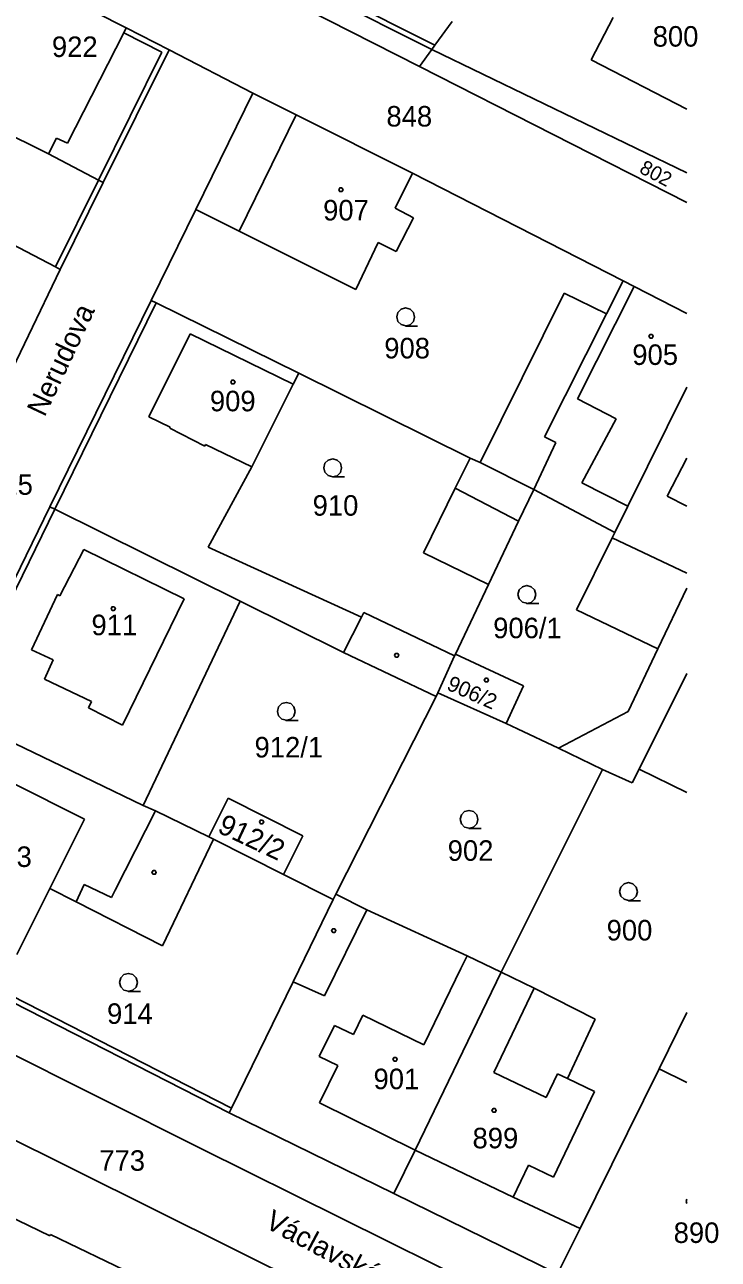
# Model space of a CAD drawing. Extents: x -621797 to -620972, y -1175539 to -1174697.
# Drawn here: x -621032.1 to -620974.5, y -1175296.1 to -1175193.8 of the extents above; entities that cross this region are included whole.
import ezdxf

# ---------------------------------------------------------------- set-up
doc = ezdxf.new("R2010")
doc.units = 0
for name, color, linetype in [('INZ mimo EON - nadz', 7, 'Continuous'), ('Rozvod plynu EON', 7, 'Continuous'), ('SDEL EON', 7, 'Continuous'), ('SDEL EON - popis', 7, 'Continuous'), ('Silnoproud EON', 7, 'Continuous'), ('Silnoproud EON - popis', 7, 'Continuous')]:
    doc.layers.add(name, color=color, linetype=linetype)

msp = doc.modelspace()

# ---------------------------------------------------------------- linework, layer by layer
at = {"layer": 'Rozvod plynu EON'}
for points in [[(-621005.74, -1175207.3), (-621005.65, -1175207.45), (-621005.74, -1175207.6), (-621005.92, -1175207.6), (-621006.01, -1175207.45), (-621005.92, -1175207.3)], [(-620980.01, -1175219.43), (-620979.92, -1175219.58), (-620980.01, -1175219.73), (-620980.19, -1175219.73), (-620980.28, -1175219.58), (-620980.19, -1175219.43)], [(-621014.7, -1175223.23), (-621014.61, -1175223.38), (-621014.7, -1175223.53), (-621014.88, -1175223.53), (-621014.97, -1175223.38), (-621014.88, -1175223.23)], [(-621024.62, -1175242), (-621024.53, -1175242.15), (-621024.62, -1175242.3), (-621024.8, -1175242.3), (-621024.89, -1175242.15), (-621024.8, -1175242)], [(-621001.12, -1175245.86), (-621001.03, -1175246.01), (-621001.12, -1175246.16), (-621001.3, -1175246.16), (-621001.39, -1175246.01), (-621001.3, -1175245.86)], [(-620993.67, -1175247.92), (-620993.58, -1175248.07), (-620993.67, -1175248.22), (-620993.85, -1175248.22), (-620993.94, -1175248.07), (-620993.85, -1175247.92)], [(-621012.32, -1175259.67), (-621012.23, -1175259.82), (-621012.32, -1175259.97), (-621012.5, -1175259.97), (-621012.59, -1175259.82), (-621012.5, -1175259.67)], [(-621021.23, -1175263.85), (-621021.14, -1175264), (-621021.23, -1175264.15), (-621021.41, -1175264.15), (-621021.5, -1175264), (-621021.41, -1175263.85)], [(-621006.33, -1175268.67), (-621006.24, -1175268.82), (-621006.33, -1175268.97), (-621006.51, -1175268.97), (-621006.6, -1175268.82), (-621006.51, -1175268.67)], [(-621001.24, -1175279.33), (-621001.15, -1175279.48), (-621001.24, -1175279.63), (-621001.42, -1175279.63), (-621001.51, -1175279.48), (-621001.42, -1175279.33)], [(-620993.03, -1175283.57), (-620992.94, -1175283.72), (-620993.03, -1175283.87), (-620993.21, -1175283.87), (-620993.3, -1175283.72), (-620993.21, -1175283.57)]]:
    msp.add_lwpolyline(points, close=True, dxfattribs=at)
at = {"layer": 'SDEL EON'}
for points in [[(-621000.45, -1175218.72), (-621000.83, -1175218.62), (-621001.1, -1175218.35), (-621001.2, -1175217.98), (-621001.1, -1175217.61), (-621000.83, -1175217.34), (-621000.46, -1175217.24), (-621000.09, -1175217.34), (-620999.82, -1175217.61), (-620999.72, -1175217.99), (-620999.82, -1175218.37), (-621000.09, -1175218.64), (-621000.47, -1175218.74), (-620999.47, -1175218.74)], [(-621006.5, -1175231.22), (-621006.88, -1175231.12), (-621007.15, -1175230.85), (-621007.25, -1175230.48), (-621007.15, -1175230.11), (-621006.88, -1175229.84), (-621006.51, -1175229.74), (-621006.14, -1175229.84), (-621005.87, -1175230.11), (-621005.77, -1175230.49), (-621005.87, -1175230.87), (-621006.14, -1175231.14), (-621006.52, -1175231.24), (-621005.52, -1175231.24)], [(-620990.4, -1175241.71), (-620990.78, -1175241.61), (-620991.05, -1175241.34), (-620991.15, -1175240.97), (-620991.05, -1175240.6), (-620990.78, -1175240.33), (-620990.41, -1175240.23), (-620990.04, -1175240.33), (-620989.77, -1175240.6), (-620989.67, -1175240.98), (-620989.77, -1175241.36), (-620990.04, -1175241.63), (-620990.42, -1175241.73), (-620989.42, -1175241.73)], [(-621010.35, -1175251.4), (-621010.73, -1175251.3), (-621011, -1175251.03), (-621011.1, -1175250.66), (-621011, -1175250.29), (-621010.73, -1175250.02), (-621010.36, -1175249.92), (-621009.99, -1175250.02), (-621009.72, -1175250.29), (-621009.62, -1175250.67), (-621009.72, -1175251.05), (-621009.99, -1175251.32), (-621010.37, -1175251.42), (-621009.37, -1175251.42)], [(-620995.19, -1175260.34), (-620995.57, -1175260.24), (-620995.84, -1175259.97), (-620995.94, -1175259.6), (-620995.84, -1175259.23), (-620995.57, -1175258.96), (-620995.2, -1175258.86), (-620994.83, -1175258.96), (-620994.56, -1175259.23), (-620994.46, -1175259.61), (-620994.56, -1175259.99), (-620994.83, -1175260.26), (-620995.21, -1175260.36), (-620994.21, -1175260.36)], [(-620981.97, -1175266.33), (-620982.35, -1175266.23), (-620982.62, -1175265.96), (-620982.72, -1175265.59), (-620982.62, -1175265.22), (-620982.35, -1175264.95), (-620981.98, -1175264.85), (-620981.61, -1175264.95), (-620981.34, -1175265.22), (-620981.24, -1175265.6), (-620981.34, -1175265.98), (-620981.61, -1175266.25), (-620981.99, -1175266.35), (-620980.99, -1175266.35)], [(-621023.44, -1175273.85), (-621023.82, -1175273.75), (-621024.09, -1175273.48), (-621024.19, -1175273.11), (-621024.09, -1175272.74), (-621023.82, -1175272.47), (-621023.45, -1175272.37), (-621023.08, -1175272.47), (-621022.81, -1175272.74), (-621022.71, -1175273.12), (-621022.81, -1175273.5), (-621023.08, -1175273.77), (-621023.46, -1175273.87), (-621022.46, -1175273.87)], [(-620977.15, -1175291.445), (-620977.2, -1175291.26), (-620977.15, -1175291.075)]]:
    msp.add_lwpolyline(points, dxfattribs=at)
at = {"layer": 'SDEL EON - popis'}
for p, q in [((-621022.58, -1175183.6), (-620998.3, -1175195.84)), ((-620998.04, -1175195.48), (-621022.32, -1175183.23)), ((-620985.07, -1175196.69), (-620983.25, -1175193.18)), ((-621023.84, -1175194.44), (-621023.64, -1175194.04)), ((-621028.51, -1175203.6), (-621023.84, -1175194.44)), ((-621020.67, -1175196.05), (-621023.84, -1175194.44)), ((-621025.93, -1175206.64), (-621020.67, -1175196.05)), ((-620977.15, -1175200.759), (-620985.07, -1175196.69)), ((-621009.53, -1175201.25), (-621014.26, -1175210.89)), ((-621030.07, -1175204.47), (-621029.42, -1175203.16)), ((-621029.42, -1175203.16), (-621028.51, -1175203.6)), ((-621029.51, -1175213.83), (-621025.93, -1175206.64)), ((-620981.5, -1175215.47), (-620986.2, -1175224.77)), ((-621029.56, -1175233.92), (-621021.15, -1175216.82)), ((-620987.32, -1175216.01), (-620994.28, -1175230.04)), ((-620983.81, -1175217.74), (-620987.32, -1175216.01)), ((-621018.32, -1175219.38), (-621021.77, -1175226.26)), ((-621009.79, -1175223.55), (-621018.32, -1175219.38)), ((-620986.2, -1175224.77), (-620983.01, -1175226.43)), ((-621021.77, -1175226.26), (-621019.99, -1175227.12)), ((-620983.01, -1175226.43), (-620985.84, -1175231.72)), ((-621019.99, -1175227.12), (-621020.02, -1175227.19)), ((-621020.02, -1175227.19), (-621017.11, -1175228.68)), ((-621017.11, -1175228.68), (-621017.05, -1175228.55)), ((-621017.05, -1175228.55), (-621013.22, -1175230.41)), ((-620995.11, -1175229.67), (-620996.35, -1175232.18)), ((-620977.15, -1175229.681), (-620978.77, -1175232.84)), ((-620996.35, -1175232.18), (-620998.99, -1175237.53)), ((-620996.35, -1175232.18), (-620991.09, -1175234.9)), ((-620985.84, -1175231.72), (-620982.03, -1175233.65)), ((-620978.77, -1175232.84), (-620977.15, -1175233.661)), ((-621037.87, -1175250.93), (-621029.56, -1175233.92)), ((-620983.33, -1175236.28), (-620977.15, -1175239.212)), ((-621029.15, -1175241.09), (-621027.15, -1175237.26)), ((-621027.15, -1175237.26), (-621018.82, -1175241.35)), ((-620998.99, -1175237.53), (-620993.59, -1175240.15)), ((-621031.5, -1175245.55), (-621029.34, -1175240.99)), ((-621029.34, -1175240.99), (-621029.15, -1175241.09)), ((-621018.82, -1175241.35), (-621023.93, -1175251.8)), ((-621004.12, -1175242.87), (-621005.6, -1175245.77)), ((-621029.68, -1175246.4), (-621031.5, -1175245.55)), ((-621030.42, -1175247.98), (-621029.68, -1175246.4)), ((-621026.52, -1175249.83), (-621030.42, -1175247.98)), ((-621026.76, -1175250.38), (-621026.52, -1175249.83)), ((-621023.93, -1175251.8), (-621026.76, -1175250.38)), ((-621027.08, -1175259.59), (-621033.2, -1175256.52)), ((-621029.98, -1175265.34), (-621027.08, -1175259.59)), ((-621021.21, -1175258.89), (-621024.54, -1175265.47)), ((-621027.12, -1175264.99), (-621027.79, -1175266.45)), ((-621024.85, -1175266.08), (-621027.12, -1175264.99)), ((-621024.54, -1175265.47), (-621024.85, -1175266.08)), ((-621003.67, -1175267.1), (-621007.2, -1175274.24)), ((-621043.01, -1175269.19), (-621014.89, -1175283.52)), ((-620995.36, -1175270.92), (-620995.87, -1175271.97)), ((-621048.05, -1175271.55), (-621017.38, -1175286.89)), ((-620995.87, -1175271.97), (-620998.96, -1175278.3)), ((-621007.2, -1175274.24), (-621009.78, -1175273.06)), ((-620989.81, -1175273.6), (-620993.15, -1175280.57)), ((-621053.99, -1175275.68), (-620977.15, -1175313.878)), ((-621004, -1175275.83), (-621004.79, -1175277.43)), ((-620998.96, -1175278.3), (-621004, -1175275.83)), ((-621006.36, -1175276.69), (-621007.63, -1175279.25)), ((-621004.79, -1175277.43), (-621006.36, -1175276.69)), ((-621007.63, -1175279.25), (-621006.07, -1175280.01)), ((-621006.07, -1175280.01), (-621007.6, -1175283.09)), ((-620993.15, -1175280.57), (-620988.82, -1175282.64)), ((-620988.82, -1175282.64), (-620987.88, -1175280.68)), ((-620987.88, -1175280.68), (-620987.03, -1175281.08)), ((-621007.6, -1175283.09), (-620999.66, -1175287)), ((-621017.38, -1175286.89), (-620977.15, -1175306.845)), ((-620999.66, -1175287), (-620991.54, -1175290.92))]:
    msp.add_line(p, q, dxfattribs=at)
at = {"layer": 'Silnoproud EON'}
for p, q in [((-620999.31, -1175197.24), (-621023.4, -1175185)), ((-621023.64, -1175194.04), (-621034.16, -1175188.68)), ((-621020.06, -1175195.86), (-621023.64, -1175194.04)), ((-620996.61, -1175193.5), (-620998.04, -1175195.48)), ((-621025.53, -1175206.85), (-621020.06, -1175195.86)), ((-621013.12, -1175199.45), (-621020.06, -1175195.86)), ((-620998.3, -1175195.84), (-620999.31, -1175197.24)), ((-620998.04, -1175195.48), (-620998.3, -1175195.84)), ((-620977.15, -1175206.036), (-620998.3, -1175195.84)), ((-620977.15, -1175208.495), (-620999.31, -1175197.24)), ((-621017.85, -1175209.08), (-621013.12, -1175199.45)), ((-621009.53, -1175201.25), (-621013.12, -1175199.45)), ((-620999.89, -1175206.07), (-621009.53, -1175201.25)), ((-621030.07, -1175204.47), (-621034.83, -1175202.12)), ((-621025.93, -1175206.64), (-621030.07, -1175204.47)), ((-621045.53, -1175205.46), (-621029.51, -1175213.83)), ((-620999.89, -1175206.07), (-621001.32, -1175208.97)), ((-620982.43, -1175215), (-620999.89, -1175206.07)), ((-621029.11, -1175214.04), (-621025.53, -1175206.85)), ((-621025.53, -1175206.85), (-621025.93, -1175206.64)), ((-621021.56, -1175216.62), (-621017.85, -1175209.08)), ((-621014.26, -1175210.89), (-621017.85, -1175209.08)), ((-621001.32, -1175208.97), (-620999.82, -1175209.76)), ((-620999.82, -1175209.76), (-621001.24, -1175212.56)), ((-621004.6, -1175215.7), (-621014.26, -1175210.89)), ((-621002.73, -1175211.81), (-621004.6, -1175215.7)), ((-621001.24, -1175212.56), (-621002.73, -1175211.81)), ((-621035.46, -1175227.24), (-621029.11, -1175214.04)), ((-621029.51, -1175213.83), (-621029.11, -1175214.04)), ((-620983.81, -1175217.74), (-620982.43, -1175215)), ((-620981.5, -1175215.47), (-620982.43, -1175215)), ((-620977.15, -1175217.693), (-620981.5, -1175215.47)), ((-621029.96, -1175233.72), (-621021.56, -1175216.62)), ((-621021.15, -1175216.82), (-621021.56, -1175216.62)), ((-621009.33, -1175222.65), (-621021.15, -1175216.82)), ((-620988.94, -1175227.93), (-620983.81, -1175217.74)), ((-621009.33, -1175222.65), (-621009.79, -1175223.55)), ((-620995.11, -1175229.67), (-621009.33, -1175222.65)), ((-621009.79, -1175223.55), (-621013.22, -1175230.41)), ((-620982.03, -1175233.65), (-620977.15, -1175223.81)), ((-620988, -1175228.39), (-620988.94, -1175227.93)), ((-620989.84, -1175232.27), (-620988, -1175228.39)), ((-620994.28, -1175230.04), (-620995.11, -1175229.67)), ((-620989.84, -1175232.27), (-620994.28, -1175230.04)), ((-621013.22, -1175230.41), (-621016.84, -1175237.05)), ((-620991.09, -1175234.9), (-620989.84, -1175232.27)), ((-620983.11, -1175235.83), (-620989.84, -1175232.27)), ((-621038.28, -1175250.73), (-621029.96, -1175233.72)), ((-621029.56, -1175233.92), (-621029.96, -1175233.72)), ((-621014.17, -1175241.53), (-621029.56, -1175233.92)), ((-620983.11, -1175235.83), (-620982.03, -1175233.65)), ((-620993.59, -1175240.15), (-620991.09, -1175234.9)), ((-620986.28, -1175242.24), (-620983.33, -1175236.28)), ((-620983.33, -1175236.28), (-620983.11, -1175235.83)), ((-621016.84, -1175237.05), (-621004.12, -1175242.87)), ((-620996.33, -1175245.92), (-620993.59, -1175240.15)), ((-620979.54, -1175245.49), (-620977.15, -1175240.452)), ((-621014.17, -1175241.53), (-621022.24, -1175258.46)), ((-621005.6, -1175245.77), (-621014.17, -1175241.53)), ((-620979.54, -1175245.49), (-620986.28, -1175242.24)), ((-621004.12, -1175242.87), (-621003.92, -1175242.48)), ((-621003.92, -1175242.48), (-620996.4, -1175246.06)), ((-620982, -1175250.66), (-620979.54, -1175245.49)), ((-620997.93, -1175249.42), (-621005.6, -1175245.77)), ((-620997.8, -1175249.12), (-620996.4, -1175246.06)), ((-620996.4, -1175246.06), (-620996.33, -1175245.92)), ((-620996.33, -1175245.92), (-620990.68, -1175248.54)), ((-620981.1, -1175255.46), (-620977.15, -1175247.515)), ((-620990.68, -1175248.54), (-620992.13, -1175251.67)), ((-621006.24, -1175265.8), (-620997.93, -1175249.42)), ((-620997.93, -1175249.42), (-620997.8, -1175249.12)), ((-620997.8, -1175249.12), (-620992.13, -1175251.67)), ((-621029.04, -1175255.18), (-621037.87, -1175250.93)), ((-620987.79, -1175253.72), (-620982, -1175250.66)), ((-620992.13, -1175251.67), (-620991.17, -1175252.1)), ((-620991.17, -1175252.1), (-620987.79, -1175253.72)), ((-620987.79, -1175253.72), (-620984.13, -1175255.48)), ((-621026.35, -1175256.48), (-621029.04, -1175255.18)), ((-620992.53, -1175272.26), (-620984.13, -1175255.48)), ((-620984.13, -1175255.48), (-620981.67, -1175256.59)), ((-620981.67, -1175256.59), (-620981.1, -1175255.46)), ((-620977.15, -1175257.387), (-620981.1, -1175255.46)), ((-621022.24, -1175258.46), (-621026.35, -1175256.48)), ((-621021.21, -1175258.89), (-621022.24, -1175258.46)), ((-621016.78, -1175261.06), (-621015.17, -1175257.85)), ((-621015.17, -1175257.85), (-621008.98, -1175260.97)), ((-621016.78, -1175261.06), (-621021.21, -1175258.89)), ((-621016.39, -1175261.25), (-621020.61, -1175270.09)), ((-621016.39, -1175261.25), (-621016.78, -1175261.06)), ((-621010.59, -1175264.18), (-621016.39, -1175261.25)), ((-621008.98, -1175260.97), (-621010.59, -1175264.18)), ((-621006.47, -1175266.26), (-621010.59, -1175264.18)), ((-621029.98, -1175265.34), (-621032.7, -1175270.8)), ((-621027.79, -1175266.45), (-621029.98, -1175265.34)), ((-621006.47, -1175266.26), (-621006.24, -1175265.8)), ((-621006.24, -1175265.8), (-621003.67, -1175267.1)), ((-621020.61, -1175270.09), (-621027.79, -1175266.45)), ((-621009.78, -1175273.06), (-621006.47, -1175266.26)), ((-621003.67, -1175267.1), (-620995.36, -1175270.92)), ((-621015.09, -1175283.92), (-621043.21, -1175269.59)), ((-620995.36, -1175270.92), (-620992.53, -1175272.26)), ((-621014.89, -1175283.52), (-621009.78, -1175273.06)), ((-620999.66, -1175287), (-620992.53, -1175272.26)), ((-620992.53, -1175272.26), (-620989.81, -1175273.6)), ((-620989.81, -1175273.6), (-620984.74, -1175276.16)), ((-620984.74, -1175276.16), (-620987.03, -1175281.08)), ((-620979.43, -1175280.27), (-620977.15, -1175275.602)), ((-620986, -1175293.49), (-620979.43, -1175280.27)), ((-620979.43, -1175280.27), (-620977.15, -1175281.398)), ((-620987.03, -1175281.08), (-620984.8, -1175282.15)), ((-620984.8, -1175282.15), (-620988.2, -1175289.25)), ((-621015.09, -1175283.92), (-621014.89, -1175283.52)), ((-621001.44, -1175290.59), (-621015.09, -1175283.92)), ((-621001.44, -1175290.59), (-620999.66, -1175287)), ((-620990.28, -1175288.26), (-620991.54, -1175290.92)), ((-620988.2, -1175289.25), (-620990.28, -1175288.26)), ((-620987.88, -1175297.25), (-621001.44, -1175290.59)), ((-620991.54, -1175290.92), (-620986, -1175293.49)), ((-621029.98, -1175294.12), (-621033.51, -1175292.41)), ((-620987.88, -1175297.25), (-620986, -1175293.49)), ((-621029.91, -1175293.99), (-621029.98, -1175294.12)), ((-621023.04, -1175297.31), (-621029.91, -1175293.99))]:
    msp.add_line(p, q, dxfattribs=at)

# ---------------------------------------------------------------- texts
at = {"layer": 'INZ mimo EON - nadz'}
for s, rotation, p in [('Nerudova', 64.80153, (-621030.398, -1175226.337)), ('Václavská', 332.08634, (-621012.227, -1175293.379))]:
    msp.add_text(s, height=1.7, rotation=rotation, dxfattribs=at).set_placement(p)
msp.add_text('773', height=1.7, dxfattribs=at).set_placement((-621025.863, -1175288.72))
at = {"layer": 'Silnoproud EON - popis'}
for s, p in [('800', (-620979.973, -1175195.59)), ('922', (-621029.793, -1175196.45)), ('848', (-621002.053, -1175202.21)), ('907', (-621007.303, -1175209.99)), ('908', (-621002.233, -1175221.42)), ('905', (-620981.663, -1175221.96)), ('909', (-621016.693, -1175225.8)), ('915', (-621035.163, -1175232.72)), ('910', (-621008.173, -1175234.45)), ('911', (-621026.513, -1175244.35)), ('906/1', (-620993.202, -1175244.6)), ('912/1', (-621012.991, -1175254.48)), ('913', (-621035.253, -1175263.55)), ('902', (-620996.973, -1175263.04)), ('900', (-620983.793, -1175269.64)), ('914', (-621025.223, -1175276.55)), ('901', (-621003.123, -1175281.96)), ('899', (-620994.913, -1175286.86)), ('890', (-620978.233, -1175294.7))]:
    msp.add_text(s, height=1.7, dxfattribs=at).set_placement(p)
for s, height, rotation, p in [('802', 1.2, 332.08634, (-620981.162, -1175205.988)), ('906/2', 1.27, 336.15434, (-620997.134, -1175248.823)), ('912/2', 1.7, 334.77924, (-621016.156, -1175260.642))]:
    msp.add_text(s, height=height, rotation=rotation, dxfattribs=at).set_placement(p)

doc.saveas('drawing.dxf')
